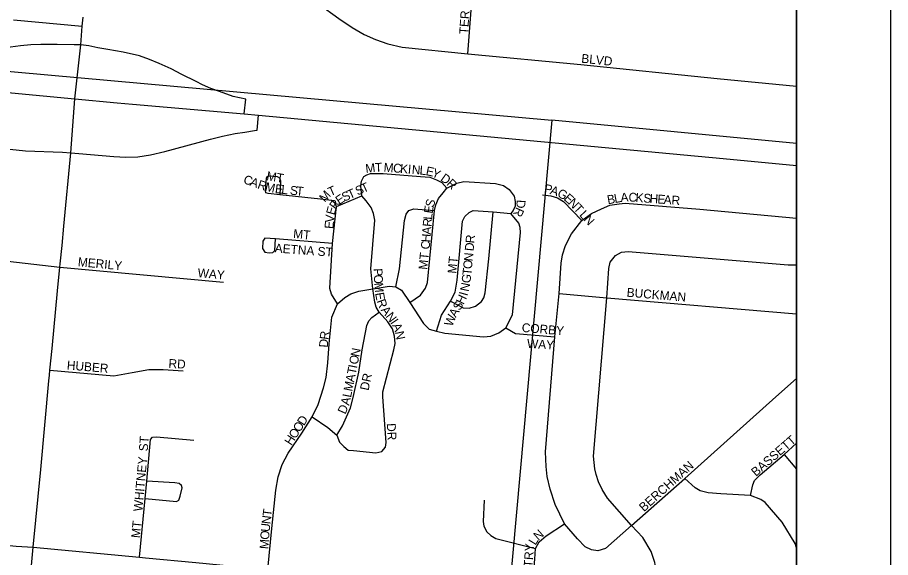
# Model space of a CAD drawing. Extents: x 8.5 to 81.5, y -1.2 to 22.4.
# Drawn here: x 55.423 to 56.353, y 17.667 to 18.242 of the extents above; entities that cross this region are included whole.
import ezdxf

# ---------------------------------------------------------------- set-up
doc = ezdxf.new("R2010")
doc.units = 0
for name, color, linetype in [('GM_X_City_Street', 7, 'Continuous'), ('GM_X_City_Street_Text', 7, 'Continuous'), ('GM_X_Corporation', 7, 'Continuous'), ('GM_X_County', 7, 'Continuous'), ('GM_X_Interchange_Ramps', 7, 'Continuous'), ('GM_X_Interstate_Route', 7, 'Continuous'), ('GM_X_Section', 7, 'Continuous'), ('GM_X_State_Route', 7, 'Continuous'), ('SH_Data', 7, 'Continuous')]:
    doc.layers.add(name, color=color, linetype=linetype)

msp = doc.modelspace()

# ---------------------------------------------------------------- linework, layer by layer
at = {"layer": 'GM_X_City_Street'}
for points in [[(55.57353, 18.37577), (55.57986, 18.37183), (55.61551, 18.34747), (55.66625, 18.31115), (55.74396, 18.25649), (55.76539, 18.24108), (55.77957, 18.23131), (55.79264, 18.22401), (55.80461, 18.21865), (55.81782, 18.21383), (55.83282, 18.21053), (55.90274, 18.20337), (56.02308, 18.19186), (56.16825, 18.17705), (56.25272, 18.16886)], [(55.90274, 18.20337), (55.90998, 18.29686)], [(55.41937, 18.2396), (55.49244, 18.23267)], [(55.79009, 18.05216), (55.78891, 18.06247), (55.78891, 18.06276), (55.78951, 18.0677), (55.7922, 18.07279), (55.79519, 18.07443), (55.79938, 18.07578), (55.81256, 18.07593), (55.85236, 18.07279), (55.86254, 18.07189), (55.86933, 18.06931), (55.87511, 18.06621), (55.88064, 18.06014)], [(55.76305, 18.04077), (55.76137, 18.04448), (55.75785, 18.04701), (55.7461, 18.04874), (55.70276, 18.05334), (55.69029, 18.05445), (55.688, 18.05545), (55.68758, 18.05784), (55.68842, 18.07105), (55.68955, 18.07273), (55.69151, 18.07343), (55.69994, 18.07273), (55.70248, 18.07118), (55.7036, 18.06795), (55.70276, 18.05334)], [(55.84108, 17.93837), (55.85258, 17.94633), (55.85775, 17.95367), (55.85999, 17.9598), (55.86732, 18.03657), (55.86867, 18.04241), (55.87152, 18.04914), (55.87661, 18.05536), (55.88064, 18.06014), (55.89097, 18.0656), (55.89875, 18.0674), (55.93227, 18.06531), (55.94095, 18.06321), (55.94694, 18.05902), (55.95203, 18.05184), (55.95323, 18.04623), (55.95323, 18.04099), (55.95113, 18.03657), (55.94844, 18.03319)], [(55.73714, 17.81675), (55.75385, 17.80544), (55.76331, 17.7972), (55.76636, 17.78972), (55.77071, 17.78514), (55.77537, 17.78141), (55.78116, 17.78095), (55.80474, 17.77841), (55.81122, 17.77981), (55.81503, 17.78461), (55.81587, 17.78953), (55.81229, 17.83809), (55.81252, 17.84328), (55.82419, 17.88828), (55.82556, 17.89477), (55.82495, 17.90278), (55.82251, 17.91057), (55.81763, 17.91781), (55.80863, 17.92826), (55.80535, 17.9336), (55.80389, 17.93894), (55.80182, 17.95312), (55.79962, 17.97449), (55.80374, 18.02637), (55.80252, 18.03316), (55.8, 18.03964), (55.79451, 18.04667), (55.79009, 18.05216)], [(55.76416, 17.93702), (55.75787, 17.94751), (55.7558, 17.95339), (55.7558, 17.95373), (55.75891, 18.00139), (55.76305, 18.04077), (55.79009, 18.05216)], [(55.98219, 18.05337), (55.99123, 18.05221), (55.99826, 18.04991), (56.0048, 18.04606), (56.02421, 18.02589)], [(55.82621, 17.95517), (55.83021, 17.97454), (55.8353, 18.02602), (55.83714, 18.03257), (55.84009, 18.03657), (55.84548, 18.0383), (55.86732, 18.03657)], [(55.8694, 17.90783), (55.87492, 17.92519), (55.88435, 17.93999), (55.88918, 17.94964), (55.89156, 17.9622), (55.89733, 18.02504), (55.8998, 18.03014), (55.90421, 18.03426), (55.90856, 18.0365), (55.92973, 18.03493), (55.94844, 18.03319)], [(56.07709, 17.70103), (56.04943, 17.67661), (56.04106, 17.67405), (56.0343, 17.67505), (56.02754, 17.67844), (56.01959, 17.68699), (56.00587, 17.70269), (55.99593, 17.72337), (55.99056, 17.73968), (55.98738, 17.7532), (55.98618, 17.76384), (55.98549, 17.77964), (55.99554, 17.90202), (55.9999, 17.94817), (56.00229, 17.98038), (56.00364, 17.98941), (56.00666, 17.99927), (56.01333, 18.0118), (56.02421, 18.02589), (56.0346, 18.03347), (56.04504, 18.03844), (56.054, 18.04203), (56.06403, 18.04371), (56.07035, 18.04429), (56.14974, 18.03795), (56.25272, 18.0285)], [(55.80436, 17.95353), (55.81902, 17.95591), (55.82621, 17.95517), (55.83222, 17.95155), (55.84108, 17.93837), (55.85547, 17.91618), (55.86153, 17.91025), (55.8694, 17.90783), (55.87836, 17.90589), (55.91942, 17.90202), (55.92717, 17.90274), (55.93571, 17.90617), (55.9434, 17.91146), (55.95048, 17.92552), (55.95897, 18.01315), (55.95866, 18.01836), (55.95694, 18.023), (55.94844, 18.03319)], [(55.88435, 17.93999), (55.89786, 17.93302), (55.90429, 17.93264), (55.91095, 17.93474), (55.91723, 17.93953), (55.91985, 17.94364), (55.92143, 17.94881), (55.92517, 17.98517), (55.92973, 18.03493)], [(55.29187, 17.99914), (55.29849, 17.9986), (55.34489, 17.99391), (55.39429, 17.98483), (55.46865, 17.97603)], [(55.75891, 18.00139), (55.69812, 18.00625), (55.6866, 18.00695), (55.68463, 18.004), (55.68435, 17.99599), (55.68673, 17.9922), (55.69138, 17.99136), (55.69517, 17.99178), (55.69742, 17.99374), (55.69812, 18.00625)], [(56.10152, 17.61496), (56.10152, 17.61502), (56.10296, 17.63197), (56.10378, 17.65112), (56.10195, 17.66171), (56.09808, 17.67333), (56.08901, 17.6882), (56.07709, 17.70103), (56.05163, 17.73017), (56.04572, 17.73934), (56.04185, 17.74769), (56.0394, 17.75523), (56.03798, 17.76154), (56.03655, 17.77483), (56.0506, 17.94359), (56.05281, 17.97457), (56.05444, 17.98151), (56.05993, 17.98872), (56.06647, 17.99218), (56.07359, 17.99276), (56.2436, 17.97852), (56.25272, 17.97869)], [(55.46865, 17.97603), (55.64264, 17.96013)], [(55.69012, 17.65404), (55.69413, 17.6977), (55.69834, 17.73873), (55.70099, 17.75299), (55.70506, 17.76603), (55.71158, 17.77805), (55.72605, 17.79944), (55.73714, 17.81675), (55.74337, 17.83), (55.74927, 17.84752), (55.752, 17.85863), (55.75371, 17.87422), (55.75532, 17.89451), (55.758, 17.92296), (55.76416, 17.93702), (55.77191, 17.94392), (55.77821, 17.94767), (55.78693, 17.9507), (55.80182, 17.95312), (55.80436, 17.95353)], [(55.9999, 17.94817), (56.0506, 17.94359), (56.25272, 17.92636)], [(55.76331, 17.7972), (55.7693, 17.80704), (55.77811, 17.82647), (55.78085, 17.83743), (55.78676, 17.86449), (55.79044, 17.88811), (55.79549, 17.91397), (55.79737, 17.91885), (55.80062, 17.9227), (55.80863, 17.92826)], [(55.9434, 17.91146), (55.95343, 17.90568), (55.99554, 17.90202)], [(55.45809, 17.86658), (55.52599, 17.86048), (55.54556, 17.86408), (55.56344, 17.86706), (55.57859, 17.86734), (55.60003, 17.86591)], [(56.07709, 17.70103), (56.13393, 17.75111), (56.23056, 17.83791), (56.25272, 17.85749)], [(55.56503, 17.79249), (55.56728, 17.79504), (55.57146, 17.79564), (55.61127, 17.7919)], [(55.55321, 17.66724), (55.5595, 17.72994), (55.56129, 17.7482), (55.56503, 17.79249)], [(56.20368, 17.73306), (56.20612, 17.74439), (56.20798, 17.74912), (56.214, 17.75501), (56.23939, 17.77652), (56.25272, 17.78863)], [(54.28539, 17.78213), (54.3418, 17.77649), (54.40794, 17.7711), (54.44995, 17.76712), (54.52451, 17.75985), (54.57011, 17.75563), (54.61506, 17.75146), (54.72158, 17.74186), (54.75564, 17.7393), (54.82745, 17.73278), (54.93731, 17.72318), (55.00257, 17.71712), (55.08622, 17.70857), (55.1814, 17.70042), (55.22457, 17.69673), (55.28322, 17.69125), (55.36713, 17.68434), (55.42202, 17.67917), (55.44021, 17.67791)], [(56.23939, 17.77652), (56.25272, 17.76119)], [(56.25272, 17.67743), (56.25116, 17.682), (56.23753, 17.70466), (56.21931, 17.7256), (56.21458, 17.72875), (56.20368, 17.73306), (56.17198, 17.73492), (56.15864, 17.73578), (56.1502, 17.73808), (56.14473, 17.74124), (56.13393, 17.75111)], [(55.5595, 17.72994), (55.59286, 17.72655), (55.59525, 17.72814), (55.59684, 17.73212), (55.59863, 17.74107), (55.59803, 17.74365), (55.59545, 17.74584), (55.59088, 17.74664), (55.56129, 17.7482)], [(55.92032, 17.72803), (55.91917, 17.70546), (55.92003, 17.70018), (55.92312, 17.6944), (55.92735, 17.69055), (55.93264, 17.68738), (55.97493, 17.67663)], [(55.97086, 17.62721), (55.9742, 17.66516), (55.97493, 17.67663), (55.97873, 17.68382), (55.98604, 17.68988), (56.00587, 17.70269)], [(55.44021, 17.67791), (55.55321, 17.66724), (55.55979, 17.6666), (55.61318, 17.66171), (55.69012, 17.65404), (55.76252, 17.64684), (55.79043, 17.6444), (55.84992, 17.6389), (55.94996, 17.62891), (55.96331, 17.62782)], [(56.25116, 17.682), (56.25272, 17.6827)]]:
    msp.add_lwpolyline(points, dxfattribs=at)
at = {"layer": 'GM_X_Corporation'}
msp.add_line((56.25272, 15.06706), (56.25272, 20.11042), dxfattribs=at)
at = {"layer": 'GM_X_County'}
msp.add_lwpolyline([(54.08792, 21.25055), (49.45272, 21.25055), (49.45272, 14.45055), (56.25272, 14.45055), (56.25272, 19.11082)], dxfattribs=at)
at = {"layer": 'GM_X_Interchange_Ramps'}
for points in [[(55.49079, 18.21298), (55.48379, 18.21298), (55.46571, 18.21335), (55.44828, 18.21336), (55.43769, 18.21279), (55.42662, 18.21188), (55.41611, 18.21058), (55.4056, 18.208), (55.34881, 18.19288), (55.33885, 18.19048), (55.32723, 18.18827), (55.31451, 18.1868), (55.3017, 18.18572), (55.30089, 18.17248)], [(55.66466, 18.13949), (55.66648, 18.15508), (55.65324, 18.15795), (55.63835, 18.16314), (55.62924, 18.16655), (55.6204, 18.17045), (55.61379, 18.17375), (55.59846, 18.18145), (55.58723, 18.18723), (55.57436, 18.19317), (55.56411, 18.19724), (55.55323, 18.20109), (55.53615, 18.20509), (55.51956, 18.208), (55.50905, 18.20984), (55.49928, 18.21188), (55.49079, 18.21298)], [(55.27532, 18.17478), (55.27339, 18.15559), (55.292, 18.15112), (55.30747, 18.14681), (55.32246, 18.14117), (55.36227, 18.12091), (55.37671, 18.11316), (55.38802, 18.10914), (55.40039, 18.10499), (55.41541, 18.10165), (55.43209, 18.09991), (55.47138, 18.0985), (55.48021, 18.09803)], [(55.48021, 18.09803), (55.48882, 18.09723), (55.52618, 18.09396), (55.53898, 18.09336), (55.55149, 18.09366), (55.56519, 18.09589), (55.58022, 18.09931), (55.62891, 18.11257), (55.64186, 18.11584), (55.65526, 18.11852), (55.66546, 18.11988), (55.67574, 18.12169), (55.67869, 18.12196), (55.67987, 18.1382)]]:
    msp.add_lwpolyline(points, dxfattribs=at)
at = {"layer": 'GM_X_Interstate_Route'}
for points in [[(54.88432, 18.19908), (54.91412, 18.20124), (54.9359, 18.20239), (54.99551, 18.20049), (55.07982, 18.19368), (55.08233, 18.19348), (55.27532, 18.17478), (55.30089, 18.17248), (55.34922, 18.16814), (55.48466, 18.15527)], [(55.48466, 18.15527), (55.52963, 18.15133), (55.54591, 18.1497), (55.66466, 18.13949), (55.67987, 18.1382), (56.17457, 18.09183), (56.25272, 18.0845)]]:
    msp.add_lwpolyline(points, dxfattribs=at)
at = {"layer": 'GM_X_Section'}
msp.add_line((56.25272, 17.09637), (56.25272, 18.10802), dxfattribs=at)
msp.add_lwpolyline([(54.98609, 18.22332), (55.99217, 18.13287), (55.90174, 17.12832), (54.89877, 17.22287)], close=True, dxfattribs=at)
msp.add_lwpolyline([(56.25272, 18.10802), (55.99217, 18.13287), (55.90174, 17.12832), (56.25272, 17.09637)], dxfattribs=at)
at = {"layer": 'GM_X_State_Route'}
for points in [[(55.48466, 18.15527), (55.49079, 18.21298), (55.49244, 18.23267), (55.49331, 18.24256)], [(55.47097, 17.99936), (55.47298, 18.01965), (55.48021, 18.09803), (55.48466, 18.15527)], [(55.46901, 17.97963), (55.47097, 17.99936)], [(55.45757, 17.86126), (55.45809, 17.86658), (55.46059, 17.88964), (55.46624, 17.95111), (55.46865, 17.97603), (55.46901, 17.97963)], [(55.32231, 16.03925), (55.33053, 16.15929), (55.33703, 16.25621), (55.34744, 16.41921), (55.35534, 16.54214), (55.36319, 16.66602), (55.37059, 16.76959), (55.37522, 16.8474), (55.38314, 16.96798), (55.38784, 17.06714), (55.396, 17.19205), (55.4007, 17.23979), (55.41275, 17.37034), (55.41563, 17.40422), (55.42383, 17.48758), (55.43205, 17.57033), (55.43672, 17.63867), (55.44021, 17.67791), (55.44836, 17.76072), (55.45699, 17.85529), (55.45757, 17.86126)]]:
    msp.add_lwpolyline(points, dxfattribs=at)
at = {"layer": 'SH_Data'}
for p, q in [((56.35272, 21.35055), (56.35272, 14.35055)), ((56.25272, 21.25055), (56.25272, 14.45055))]:
    msp.add_line(p, q, dxfattribs=at)

# ---------------------------------------------------------------- texts
at = {"layer": 'GM_X_City_Street_Text'}
for s, height, rotation, p in [('TERMINAL PL', 0.0094697, 86.22991, (55.90304, 18.22395)), ('BLVD', 0.00947, 354.14185, (56.02329, 18.19394)), ('M', 0.00947, 6.64387, (55.79436, 18.07641)), ('T', 0.00947, 2.73281, (55.80413, 18.07755)), ('M', 0.00947, 356.08051, (55.813, 18.07791)), ('C', 0.00947, 355.11335, (55.82293, 18.07723)), ('K', 0.00947, 355.13896, (55.83041, 18.07659)), ('I', 0.00947, 355.09842, (55.83871, 18.07589)), ('N', 0.00947, 355.13896, (55.84287, 18.07553)), ('L', 0.00947, 355.13201, (55.85117, 18.07482)), ('E', 0.00947, 348.25066, (55.85752, 18.0743)), ('C', 0.00947, 339.8675, (55.66314, 18.06589)), ('MT', 0.00947, 350.46856, (55.68805, 18.06895)), ('Y', 0.00947, 336.83872, (55.86357, 18.07309)), ('D', 0.00947, 324.64272, (55.87297, 18.06889)), ('A', 0.00947, 339.89096, (55.67019, 18.06331)), ('R', 0.00947, 341.13224, (55.67823, 18.06037)), ('M', 0.00947, 346.93695, (55.68633, 18.05765)), ('E', 0.00947, 353.35811, (55.69721, 18.0552)), ('T', 0.00947, 24.27744, (55.79166, 18.05501)), ('R', 0.00947, 317.04357, (55.8795, 18.06428)), ('P', 0.00947, 347.97203, (55.98343, 18.05559)), ('L', 0.00947, 354.04543, (55.70396, 18.05441)), ('S', 0.00947, 354.42828, (55.71315, 18.05347)), ('T', 0.00947, 354.47756, (55.71979, 18.05282)), ('M', 0.00947, 47.97623, (55.75069, 18.04466)), ('T', 0.00947, 23.61842, (55.75653, 18.05147)), ('S', 0.00947, 24.27744, (55.77115, 18.04576)), ('T', 0.00947, 24.27744, (55.77722, 18.0485)), ('S', 0.00947, 24.27744, (55.78558, 18.05227)), ('A', 0.00947, 341.5374, (55.98968, 18.05427)), ('G', 0.00947, 333.51316, (55.99726, 18.05177)), ('A', 0.00947, 4.50768, (56.06566, 18.04553)), ('C', 0.00947, 356.42821, (56.07361, 18.04618)), ('K', 0.00947, 355.95331, (56.08108, 18.04572)), ('R', 0.00947, 54.48033, (55.76229, 18.03672)), ('E', 0.00947, 34.34507, (55.76602, 18.04221)), ('S', 0.00947, 73.14635, (55.86624, 18.03908)), ('D', 0.00947, 266.15103, (55.9549, 18.04817)), ('E', 0.00947, 318.82693, (56.00418, 18.04841)), ('N', 0.00947, 313.33077, (56.00903, 18.04418)), ('B', 0.00947, 10.08113, (56.05195, 18.04308)), ('L', 0.00947, 10.07761, (56.05933, 18.0444)), ('S', 0.00947, 355.97555, (56.08939, 18.04513)), ('H', 0.00947, 355.97319, (56.09604, 18.04466)), ('E', 0.00947, 355.98056, (56.10436, 18.04408)), ('A', 0.00947, 355.95331, (56.11101, 18.04361)), ('R', 0.00947, 355.97328, (56.11932, 18.04302)), ('E', 0.00947, 74.61559, (55.7609, 18.03109)), ('E', 0.00947, 81.22475, (55.8653, 18.03284)), ('R', 0.00947, 245.71687, (55.95455, 18.04071)), ('T', 0.00947, 312.56582, (56.01472, 18.03815)), ('L', 0.00947, 312.59272, (56.02093, 18.03139)), ('V', 0.00947, 84.68322, (55.76021, 18.02322)), ('R', 0.00947, 85.25854, (55.86416, 18.01889)), ('L', 0.00947, 85.30273, (55.86478, 18.02637)), ('N', 0.00947, 312.59492, (56.02544, 18.02648)), ('E', 0.00947, 84.68322, (55.75959, 18.01658)), ('A', 0.00947, 85.28568, (55.86347, 18.01058)), ('MT', 0.00947, 354.5523, (55.71661, 18.00727)), ('H', 0.00947, 85.27446, (55.86279, 18.00228)), ('R', 0.00947, 84.64893, (55.90968, 18.00121)), ('AETNA ST', 0.00947, 355.73128, (55.69703, 17.99187)), ('C', 0.00947, 85.28274, (55.86217, 17.9948)), ('D', 0.00947, 84.64317, (55.9089, 17.99291)), ('MT', 0.00947, 84.56261, (55.85967, 17.97317)), ('N', 0.00947, 84.63123, (55.90789, 17.98212)), ('MERILY', 0.00947, 354.60969, (55.48745, 17.97727)), ('MT', 0.00947, 84.55229, (55.89051, 17.969)), ('O', 0.00947, 84.58628, (55.9071, 17.97382)), ('WAY', 0.00947, 354.80796, (55.61494, 17.96561)), ('P', 0.00947, 272.62366, (55.80239, 17.97472)), ('T', 0.00947, 84.15846, (55.90641, 17.96711)), ('O', 0.00947, 272.63077, (55.8027, 17.96806)), ('G', 0.00947, 83.24274, (55.90542, 17.95867)), ('M', 0.00947, 275.06928, (55.80311, 17.95929)), ('N', 0.00947, 78.47437, (55.90361, 17.94965)), ('BUCKMAN', 0.00947, 355.16937, (56.07159, 17.94478)), ('E', 0.00947, 279.90858, (55.80411, 17.94847)), ('H', 0.00947, 64.644, (55.89813, 17.93575)), ('I', 0.00947, 74.35075, (55.90231, 17.94492)), ('R', 0.00947, 289.51923, (55.80569, 17.94022)), ('S', 0.00947, 59.85254, (55.89438, 17.92922)), ('A', 0.00947, 307.6669, (55.80976, 17.93029)), ('N', 0.00947, 307.74614, (55.81486, 17.92368)), ('W', 0.00947, 68.24541, (55.88619, 17.91225)), ('A', 0.00947, 59.05123, (55.89002, 17.92195)), ('I', 0.00947, 303.61736, (55.81986, 17.91724)), ('CORBY', 0.00947, 355.239, (55.95993, 17.90727)), ('R', 0.00947, 82.35078, (55.75442, 17.89848)), ('A', 0.00947, 294.78583, (55.82198, 17.9141)), ('N', 0.00947, 281.68716, (55.82529, 17.90708)), ('D', 0.00947, 85.79913, (55.75382, 17.89032)), ('WAY', 0.00947, 356.53377, (55.96557, 17.89018)), ('N', 0.00947, 78.55393, (55.78718, 17.8801)), ('RD', 0.00947, 356.98902, (55.58404, 17.86895)), ('O', 0.00947, 78.55393, (55.78553, 17.87193)), ('HUBER', 0.00947, 355.13362, (55.47576, 17.86728)), ('T', 0.00947, 78.57554, (55.78339, 17.86131)), ('I', 0.00947, 78.5615, (55.78471, 17.86784)), ('A', 0.00947, 78.56692, (55.78173, 17.85314)), ('DR', 0.00947, 78.11829, (55.79714, 17.84422)), ('M', 0.00947, 78.55788, (55.77975, 17.84334)), ('L', 0.00947, 78.59103, (55.77843, 17.8368)), ('A', 0.00947, 76.80077, (55.77646, 17.82838)), ('D', 0.00947, 65.72243, (55.77239, 17.81889)), ('D', 0.00947, 57.48464, (55.72838, 17.80672)), ('O', 0.00947, 57.48464, (55.71942, 17.79267)), ('O', 0.00947, 57.48464, (55.7239, 17.79969)), ('DR', 0.00947, 273.01099, (55.81655, 17.80976)), ('ST', 0.00947, 86.18785, (55.56217, 17.77979)), ('H', 0.00947, 57.48018, (55.71494, 17.78564)), ('BASSETT', 0.00947, 41.00637, (56.20946, 17.7527)), ('WHITNEY', 0.00947, 84.72507, (55.55635, 17.71571)), ('BERCHMAN', 0.00947, 41.93518, (56.09025, 17.71516)), ('N', 0.00947, 82.92376, (55.69267, 17.70209)), ('T', 0.00947, 82.87837, (55.69369, 17.71036)), ('MT', 0.00947, 84.55229, (55.55384, 17.68734)), ('U', 0.00947, 84.39596, (55.69186, 17.69386)), ('O', 0.00947, 85.73652, (55.69124, 17.68561)), ('N', 0.00947, 41.41209, (55.97778, 17.68454)), ('M', 0.00947, 85.71584, (55.6905, 17.67563)), ('L', 0.00947, 58.25822, (55.97474, 17.67943)), ('GENTRY', 0.00947, 85.91271, (55.96967, 17.62896))]:
    msp.add_text(s, height=height, rotation=rotation, dxfattribs=at).set_placement(p)

doc.saveas('drawing.dxf')
